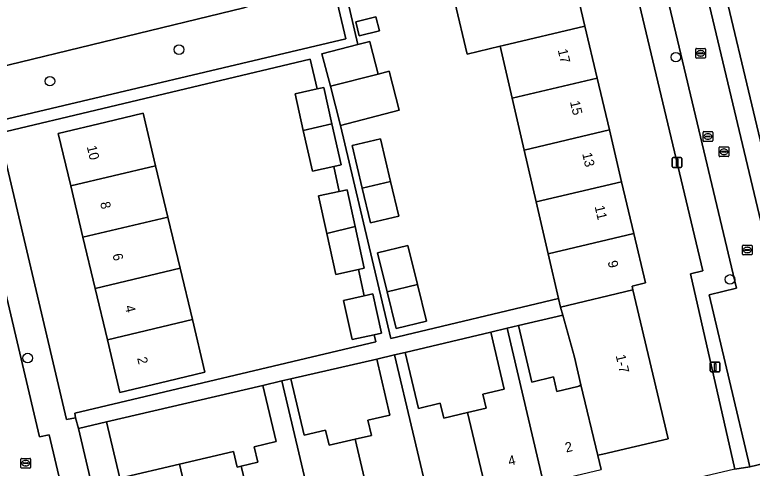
# Model space of a CAD drawing. Extents: x 158472 to 159562, y 388525 to 389606.
# Drawn here: x 159171.7 to 159247.3, y 388576.2 to 388622.7 of the extents above; entities that cross this region are included whole.
import ezdxf

# ---------------------------------------------------------------- set-up
doc = ezdxf.new("R2010")
doc.units = 0
for name, color, linetype in [('IMGEO_Boom', 7, 'Continuous'), ('IMGEO_Erf', 7, 'Continuous'), ('IMGEO_Groenvoorziening', 7, 'Continuous'), ('IMGEO_Kolk', 7, 'Continuous'), ('IMGEO_Lichtmast', 7, 'Continuous'), ('IMGEO_Pand', 7, 'Continuous'), ('IMGEO_Pand_nummerreeks', 7, 'Continuous'), ('IMGEO_Rijbaan_lokaal_open', 7, 'Continuous'), ('IMGEO_Rioolput', 7, 'Continuous'), ('IMGEO_Voetpad_open', 7, 'Continuous')]:
    doc.layers.add(name, color=color, linetype=linetype)

msp = doc.modelspace()

# ---------------------------------------------------------------- linework, layer by layer
at = {"layer": 'IMGEO_Boom'}
for centre in [(159188.531, 388619.113), (159239.452, 388618.341), (159175.308, 388615.879), (159245.003, 388595.558), (159173.023, 388587.499)]:
    msp.add_circle(centre, 0.489, dxfattribs=at)
at = {"layer": 'IMGEO_Erf'}
for points in [[(159296.887, 388671.93), (159244.148, 388659.578), (159237.861, 388658.105), (159242.256, 388639.554), (159241.15, 388639.006), (159241.895, 388635.876), (159249.79, 388602.69), (159251.019, 388602.978), (159251.382, 388603.063), (159252.961, 388596.326), (159253.582, 388593.966)], [(159245.514, 388576.124), (159240.949, 388596.135), (159242.23, 388596.442), (159229.574, 388649.566)], [(159201.454, 388642.922), (159206.868, 388619.642), (159207.813, 388619.885), (159208.079, 388619.953), (159208.123, 388619.781), (159208.936, 388616.616), (159210.069, 388616.907), (159211.098, 388612.898), (159205.074, 388611.351), (159210.232, 388589.51), (159227.434, 388593.617), (159226.379, 388598.185), (159225.149, 388603.504), (159223.918, 388608.825), (159222.688, 388614.145), (159221.459, 388619.464), (159218.069, 388618.665), (159216.817, 388623.98)], [(159228.886, 388626.824), (159230.138, 388621.509), (159231.39, 388616.195), (159232.642, 388610.88), (159233.894, 388605.565), (159235.146, 388600.251), (159236.335, 388595.203), (159234.971, 388594.882), (159235.061, 388594.501), (159238.659, 388579.224), (159231.965, 388577.646), (159231.645, 388577.571), (159231.445, 388577.524), (159231.791, 388576.064)]]:
    msp.add_lwpolyline(points, dxfattribs=at)
for points in [[(159206.652, 388621.955), (159208.709, 388622.473), (159209.071, 388621.035), (159207.014, 388620.518)], [(159203.683, 388600.277), (159202.841, 388604.12), (159204.95, 388604.582), (159204.39, 388607.136), (159202.213, 388606.645), (159201.273, 388610.823), (159200.428, 388614.575), (159202.693, 388615.085), (159201.971, 388618.129), (159170.055, 388610.56), (159177.021, 388581.185), (159177.94, 388581.388), (159177.865, 388581.835), (159208.71, 388589.15), (159208.535, 388589.892), (159206.267, 388589.397), (159205.392, 388593.406), (159207.506, 388593.867), (159206.913, 388596.581), (159204.603, 388596.075)], [(159188.648, 388596.696), (159189.901, 388591.435), (159191.182, 388586.055), (159187.346, 388585.141), (159182.482, 388583.983), (159181.201, 388589.363), (159179.948, 388594.624), (159178.695, 388599.886), (159177.442, 388605.147), (159176.161, 388610.525), (159181.025, 388611.683), (159184.861, 388612.597), (159186.142, 388607.219), (159187.395, 388601.957)], [(159209.176, 388609.966), (159210.207, 388605.595), (159211.047, 388602.037), (159208.145, 388601.352), (159207.306, 388604.912), (159206.275, 388609.281)], [(159212.972, 388595.026), (159213.895, 388591.28), (159210.792, 388590.514), (159209.86, 388594.292), (159208.878, 388598.277), (159211.981, 388599.043)], [(159227.87, 388591.894), (159223.33, 388590.824), (159224.693, 388585.038), (159226.917, 388585.562), (159227.265, 388584.086), (159229.405, 388584.59), (159229.516, 388584.616), (159229.73, 388584.76), (159229.058, 388587.593)], [(159220.494, 388590.156), (159211.727, 388588.073), (159213.077, 388582.342), (159215.311, 388582.869), (159215.674, 388581.328), (159218.116, 388581.903), (159220.023, 388582.352), (159219.68, 388583.807), (159221.869, 388584.323)], [(159208.793, 388587.382), (159199.992, 388585.371), (159201.356, 388579.58), (159203.564, 388580.1), (159203.928, 388578.554), (159206.583, 388579.18), (159208.257, 388579.574), (159207.892, 388581.123), (159210.142, 388581.653)], [(159197.12, 388584.695), (159181.114, 388580.966), (159182.479, 388575.171), (159188.571, 388576.606), (159194.124, 388577.914), (159194.499, 388576.324), (159194.9, 388576.419), (159196.607, 388576.821), (159196.233, 388578.412), (159198.476, 388578.94)]]:
    msp.add_lwpolyline(points, close=True, dxfattribs=at)
at = {"layer": 'IMGEO_Groenvoorziening'}
msp.add_lwpolyline([(159168.435, 388620.55), (159168.696, 388616.985), (159195.192, 388623.391), (159195.688, 388623.56), (159196.139, 388623.829), (159196.524, 388624.186), (159196.826, 388624.615), (159197.032, 388625.097), (159197.134, 388625.611), (159197.042, 388626.545), (159194.87, 388640.508), (159199.815, 388642.509), (159199.819, 388643.8), (159199.82, 388643.968), (159199.978, 388645.419), (159200.286, 388646.845), (159200.742, 388648.231), (159201.34, 388649.562), (159202.074, 388650.824), (159202.936, 388652.001), (159204.476, 388653.608), (159199.027, 388656.284)], dxfattribs=at)
msp.add_lwpolyline([(159169.776, 388611.735), (159205.64, 388620.22), (159200.073, 388643.862), (159199.819, 388643.8), (159199.815, 388642.509), (159194.87, 388640.508), (159197.042, 388626.545), (159197.134, 388625.611), (159197.032, 388625.097), (159196.826, 388624.615), (159196.524, 388624.186), (159196.139, 388623.829), (159195.688, 388623.56), (159195.192, 388623.391), (159168.696, 388616.985)], close=True, dxfattribs=at)
at = {"layer": 'IMGEO_Kolk'}
for p, q in [((159241.488, 388618.31), (159241.488, 388619.162)), ((159241.563, 388619.236), (159242.415, 388619.236)), ((159241.747, 388618.73), (159241.747, 388618.742)), ((159242.185, 388618.693), (159241.787, 388618.693)), ((159241.79, 388618.779), (159242.188, 388618.779)), ((159241.976, 388619.016), (159242.001, 388619.016)), ((159242.231, 388618.742), (159242.231, 388618.73)), ((159242.489, 388619.162), (159242.489, 388618.31)), ((159242.415, 388618.236), (159241.563, 388618.236)), ((159241.999, 388618.456), (159241.974, 388618.456)), ((159243.879, 388608.223), (159243.879, 388609.075)), ((159243.954, 388609.149), (159244.806, 388609.149)), ((159244.367, 388608.929), (159244.392, 388608.929)), ((159244.88, 388609.075), (159244.88, 388608.223)), ((159244.806, 388608.149), (159243.954, 388608.149)), ((159244.138, 388608.643), (159244.138, 388608.655)), ((159244.576, 388608.606), (159244.178, 388608.606)), ((159244.181, 388608.692), (159244.579, 388608.692)), ((159244.39, 388608.369), (159244.365, 388608.369)), ((159244.622, 388608.655), (159244.622, 388608.643)), ((159246.344, 388599.075), (159247.196, 388599.075)), ((159246.269, 388598.149), (159246.269, 388599.001)), ((159246.528, 388598.569), (159246.528, 388598.581)), ((159246.966, 388598.532), (159246.568, 388598.532)), ((159246.571, 388598.618), (159246.969, 388598.618)), ((159246.78, 388598.295), (159246.755, 388598.295)), ((159246.757, 388598.855), (159246.782, 388598.855)), ((159247.012, 388598.581), (159247.012, 388598.569)), ((159247.27, 388599.001), (159247.27, 388598.149)), ((159247.196, 388598.075), (159246.344, 388598.075)), ((159172.321, 388576.292), (159172.321, 388577.144)), ((159172.396, 388577.218), (159173.248, 388577.218)), ((159173.322, 388577.144), (159173.322, 388576.292)), ((159172.58, 388576.712), (159172.58, 388576.724)), ((159173.018, 388576.675), (159172.62, 388576.675)), ((159172.623, 388576.761), (159173.021, 388576.761)), ((159172.832, 388576.438), (159172.807, 388576.438)), ((159172.809, 388576.998), (159172.834, 388576.998)), ((159173.064, 388576.724), (159173.064, 388576.712)), ((159173.248, 388576.218), (159172.396, 388576.218))]:
    msp.add_line(p, q, dxfattribs=at)
for points in [[(159241.488, 388618.31), (159241.488, 388619.162)], [(159241.563, 388619.236), (159242.415, 388619.236)], [(159242.489, 388619.162), (159242.489, 388618.31)], [(159242.415, 388618.236), (159241.563, 388618.236)], [(159243.879, 388608.223), (159243.879, 388609.075)], [(159243.954, 388609.149), (159244.806, 388609.149)], [(159244.88, 388609.075), (159244.88, 388608.223)], [(159244.806, 388608.149), (159243.954, 388608.149)], [(159246.344, 388599.075), (159247.196, 388599.075)], [(159246.269, 388598.149), (159246.269, 388599.001)], [(159247.27, 388599.001), (159247.27, 388598.149)], [(159247.196, 388598.075), (159246.344, 388598.075)], [(159172.321, 388576.292), (159172.321, 388577.144)], [(159172.396, 388577.218), (159173.248, 388577.218)], [(159173.322, 388577.144), (159173.322, 388576.292)], [(159173.248, 388576.218), (159172.396, 388576.218)]]:
    msp.add_lwpolyline(points, dxfattribs=at)
for centre, radius, start, end in [((159241.565, 388619.16), 0.0765, 91.55205, 178.44795), ((159241.565, 388619.16), 0.0765, 91.55205, 178.44795), ((159241.787, 388618.739), 0.0403, 85.87752, 175.75265), ((159241.784, 388618.729), 0.0366, 178.93798, 274.71019), ((159242.188, 388618.736), 0.043, 264.86636, 352.45326), ((159242.192, 388618.741), 0.0386, 1.73085, 96.63898), ((159242.413, 388619.16), 0.0765, 1.55205, 88.44795), ((159242.413, 388619.16), 0.0765, 1.55205, 88.44795), ((159241.565, 388618.312), 0.0765, 181.55205, 268.44795), ((159241.565, 388618.312), 0.0765, 181.55205, 268.44795), ((159242.413, 388618.312), 0.0765, 271.55205, 358.44795), ((159242.413, 388618.312), 0.0765, 271.55205, 358.44795), ((159243.956, 388609.073), 0.0765, 91.55205, 178.44795), ((159243.956, 388609.073), 0.0765, 91.55205, 178.44795), ((159244.804, 388609.073), 0.0765, 1.55205, 88.44795), ((159244.804, 388609.073), 0.0765, 1.55205, 88.44795), ((159243.956, 388608.225), 0.0765, 181.55205, 268.44795), ((159243.956, 388608.225), 0.0765, 181.55205, 268.44795), ((159244.178, 388608.652), 0.0403, 85.87752, 175.75265), ((159244.175, 388608.642), 0.0366, 178.93798, 274.71019), ((159244.579, 388608.649), 0.043, 264.86636, 352.45326), ((159244.583, 388608.654), 0.0386, 1.73085, 96.63898), ((159244.804, 388608.225), 0.0765, 271.55205, 358.44795), ((159244.804, 388608.225), 0.0765, 271.55205, 358.44795), ((159246.346, 388598.999), 0.0765, 91.55205, 178.44795), ((159246.346, 388598.999), 0.0765, 91.55205, 178.44795), ((159247.194, 388598.999), 0.0765, 1.55205, 88.44795), ((159247.194, 388598.999), 0.0765, 1.55205, 88.44795), ((159246.568, 388598.578), 0.0403, 85.87752, 175.75265), ((159246.565, 388598.568), 0.0366, 178.93798, 274.71019), ((159246.969, 388598.575), 0.043, 264.86636, 352.45326), ((159246.973, 388598.58), 0.0386, 1.73085, 96.63898), ((159246.346, 388598.151), 0.0765, 181.55205, 268.44795), ((159246.346, 388598.151), 0.0765, 181.55205, 268.44795), ((159247.194, 388598.151), 0.0765, 271.55205, 358.44795), ((159247.194, 388598.151), 0.0765, 271.55205, 358.44795), ((159172.398, 388577.142), 0.0765, 91.55205, 178.44795), ((159172.398, 388577.142), 0.0765, 91.55205, 178.44795), ((159173.246, 388577.142), 0.0765, 1.55205, 88.44795), ((159173.246, 388577.142), 0.0765, 1.55205, 88.44795), ((159172.62, 388576.721), 0.0403, 85.87752, 175.75265), ((159172.617, 388576.711), 0.0366, 178.93798, 274.71019), ((159173.021, 388576.718), 0.043, 264.86636, 352.45326), ((159173.025, 388576.723), 0.0386, 1.73085, 96.63898), ((159172.398, 388576.294), 0.0765, 181.55205, 268.44795), ((159172.398, 388576.294), 0.0765, 181.55205, 268.44795), ((159173.246, 388576.294), 0.0765, 271.55205, 358.44795), ((159173.246, 388576.294), 0.0765, 271.55205, 358.44795)]:
    msp.add_arc(centre, radius, start, end, dxfattribs=at)
for centre, major_axis, ratio, start_param, end_param in [((159241.975, 388618.736), (-0.387, 0.002), 0.722429, 4.712389, 7.853982), ((159242, 388618.736), (-0.39, 0.002), 0.717154, 1.570796, 4.712389), ((159244.366, 388608.649), (-0.387, 0.002), 0.722429, 4.712389, 7.853982), ((159244.391, 388608.649), (-0.39, 0.002), 0.717154, 1.570796, 4.712389), ((159246.756, 388598.575), (-0.387, 0.002), 0.722429, 4.712389, 7.853982), ((159246.781, 388598.575), (-0.39, 0.002), 0.717154, 1.570796, 4.712389), ((159172.808, 388576.718), (-0.387, 0.002), 0.722429, 4.712389, 7.853982), ((159172.833, 388576.718), (-0.39, 0.002), 0.717154, 1.570796, 4.712389)]:
    msp.add_ellipse(centre, major_axis=major_axis, ratio=ratio, start_param=start_param, end_param=end_param, dxfattribs=at)
at = {"layer": 'IMGEO_Lichtmast'}
for p, q in [((159239.088, 388607.146), (159239.088, 388607.946)), ((159239.088, 388607.946), (159239.088, 388607.146)), ((159239.188, 388608.046), (159239.978, 388608.046)), ((159239.978, 388608.046), (159239.188, 388608.046)), ((159240.078, 388607.946), (159240.078, 388607.146)), ((159240.078, 388607.146), (159240.078, 388607.946)), ((159239.978, 388607.046), (159239.188, 388607.046)), ((159239.188, 388607.046), (159239.978, 388607.046)), ((159242.987, 388586.177), (159242.987, 388586.977)), ((159242.987, 388586.977), (159242.987, 388586.177)), ((159243.087, 388587.077), (159243.877, 388587.077)), ((159243.877, 388587.077), (159243.087, 388587.077)), ((159243.977, 388586.977), (159243.977, 388586.177)), ((159243.977, 388586.177), (159243.977, 388586.977)), ((159243.877, 388586.077), (159243.087, 388586.077)), ((159243.087, 388586.077), (159243.877, 388586.077))]:
    msp.add_line(p, q, dxfattribs=at)
for points in [[(159239.508, 388607.921), (159239.658, 388607.921), (159239.658, 388607.171), (159239.508, 388607.171), (159239.508, 388607.921)], [(159243.407, 388586.952), (159243.557, 388586.952), (159243.557, 388586.202), (159243.407, 388586.202), (159243.407, 388586.952)]]:
    msp.add_lwpolyline(points, dxfattribs=at)
for centre, start, end in [((159239.188, 388607.946), 90, 180), ((159239.188, 388607.946), 90, 180), ((159239.978, 388607.946), 0, 90), ((159239.978, 388607.946), 360, 90), ((159239.188, 388607.146), 180, 270), ((159239.188, 388607.146), 180, 270), ((159239.978, 388607.146), 270, 0), ((159239.978, 388607.146), 270, 0), ((159243.087, 388586.977), 90, 180), ((159243.087, 388586.977), 90, 180), ((159243.877, 388586.977), 0, 90), ((159243.877, 388586.977), 360, 90), ((159243.087, 388586.177), 180, 270), ((159243.087, 388586.177), 180, 270), ((159243.877, 388586.177), 270, 0), ((159243.877, 388586.177), 270, 0)]:
    msp.add_arc(centre, 0.1, start, end, dxfattribs=at)
at = {"layer": 'IMGEO_Pand'}
for points in [[(159228.886, 388626.824), (159220.229, 388624.784), (159216.817, 388623.98), (159218.069, 388618.665), (159221.459, 388619.464), (159221.761, 388619.535), (159230.138, 388621.509)], [(159206.652, 388621.955), (159207.014, 388620.518), (159209.071, 388621.035), (159208.709, 388622.473)], [(159230.138, 388621.509), (159221.761, 388619.535), (159221.459, 388619.464), (159222.688, 388614.145), (159231.39, 388616.195)], [(159208.123, 388619.781), (159208.079, 388619.953), (159207.813, 388619.885), (159206.868, 388619.642), (159203.187, 388618.698), (159204.045, 388615.359), (159208.936, 388616.616)], [(159208.936, 388616.616), (159204.045, 388615.359), (159205.074, 388611.351), (159211.098, 388612.898), (159210.069, 388616.907)], [(159222.688, 388614.145), (159223.918, 388608.825), (159232.642, 388610.88), (159231.39, 388616.195)], [(159203.372, 388615.238), (159202.693, 388615.085), (159200.428, 388614.575), (159201.273, 388610.823), (159204.209, 388611.522)], [(159186.142, 388607.219), (159184.861, 388612.597), (159181.025, 388611.683), (159176.161, 388610.525), (159177.442, 388605.147)], [(159204.209, 388611.522), (159201.273, 388610.823), (159202.213, 388606.645), (159204.39, 388607.136), (159205.158, 388607.309)], [(159225.149, 388603.504), (159233.894, 388605.565), (159232.642, 388610.88), (159223.918, 388608.825)], [(159210.207, 388605.595), (159209.176, 388609.966), (159206.275, 388609.281), (159207.306, 388604.912)], [(159186.142, 388607.219), (159177.442, 388605.147), (159178.695, 388599.886), (159187.395, 388601.957)], [(159210.207, 388605.595), (159207.306, 388604.912), (159208.145, 388601.352), (159211.047, 388602.037)], [(159226.379, 388598.185), (159235.146, 388600.251), (159233.894, 388605.565), (159225.149, 388603.504)], [(159205.753, 388604.758), (159204.95, 388604.582), (159202.841, 388604.12), (159203.683, 388600.277), (159206.583, 388600.968)], [(159188.648, 388596.696), (159187.395, 388601.957), (159178.695, 388599.886), (159179.948, 388594.624)], [(159206.583, 388600.968), (159203.683, 388600.277), (159204.603, 388596.075), (159206.913, 388596.581), (159207.515, 388596.713)], [(159235.146, 388600.251), (159226.379, 388598.185), (159227.434, 388593.617), (159227.639, 388592.731), (159235.061, 388594.501), (159234.971, 388594.882), (159236.335, 388595.203)], [(159209.86, 388594.292), (159212.972, 388595.026), (159211.981, 388599.043), (159208.878, 388598.277)], [(159188.648, 388596.696), (159179.948, 388594.624), (159181.201, 388589.363), (159189.901, 388591.435)], [(159209.86, 388594.292), (159210.792, 388590.514), (159213.895, 388591.28), (159212.972, 388595.026)], [(159235.061, 388594.501), (159227.639, 388592.731), (159227.87, 388591.894), (159229.058, 388587.593), (159229.73, 388584.76), (159231.445, 388577.524), (159231.645, 388577.571), (159231.965, 388577.646), (159238.659, 388579.224)], [(159208.411, 388594.065), (159207.506, 388593.867), (159205.392, 388593.406), (159206.267, 388589.397), (159208.535, 388589.892), (159209.286, 388590.056)], [(159181.201, 388589.363), (159182.482, 388583.983), (159187.346, 388585.141), (159191.182, 388586.055), (159189.901, 388591.435)], [(159229.73, 388584.76), (159229.516, 388584.616), (159229.405, 388584.59), (159227.265, 388584.086), (159226.917, 388585.562), (159224.693, 388585.038), (159223.33, 388590.824), (159222.167, 388590.55), (159225.906, 388574.678), (159231.791, 388576.064), (159231.445, 388577.524)], [(159222.167, 388590.55), (159220.494, 388590.156), (159221.869, 388584.323), (159219.68, 388583.807), (159220.023, 388582.352), (159218.116, 388581.903), (159220.138, 388573.319), (159225.906, 388574.678)], [(159214.371, 388571.961), (159210.636, 388587.816), (159208.793, 388587.382), (159210.142, 388581.653), (159207.892, 388581.123), (159208.257, 388579.574), (159206.583, 388579.18), (159208.604, 388570.602)], [(159214.371, 388571.961), (159220.138, 388573.319), (159218.116, 388581.903), (159215.674, 388581.328), (159215.311, 388582.869), (159213.077, 388582.342), (159211.727, 388588.073), (159210.636, 388587.816)], [(159199.087, 388585.158), (159197.12, 388584.695), (159198.476, 388578.94), (159196.233, 388578.412), (159196.607, 388576.821), (159194.9, 388576.419), (159196.956, 388567.858), (159202.836, 388569.243)], [(159206.583, 388579.18), (159203.928, 388578.554), (159203.564, 388580.1), (159201.356, 388579.58), (159199.992, 388585.371), (159199.087, 388585.158), (159202.836, 388569.243), (159208.604, 388570.602)], [(159190.964, 388566.447), (159188.571, 388576.606), (159182.479, 388575.171), (159181.114, 388580.966), (159178.232, 388580.287), (159181.007, 388568.502), (159183.994, 388569.205), (159184.976, 388565.036), (159188.471, 388565.859)], [(159190.964, 388566.447), (159193.194, 388566.972), (159196.956, 388567.858), (159194.9, 388576.419), (159194.499, 388576.324), (159194.124, 388577.914), (159188.571, 388576.606)]]:
    msp.add_lwpolyline(points, close=True, dxfattribs=at)
at = {"layer": 'IMGEO_Rijbaan_lokaal_open'}
for points in [[(159237.637, 388645.762), (159233.744, 388644.836), (159245.683, 388594.649), (159242.861, 388593.978), (159247.052, 388576.361), (159253.767, 388577.959)], [(159167.373, 388608.491), (159161.72, 388607.241), (159164.57, 388595.141), (159166.293, 388595.522), (159166.762, 388593.532), (159165.038, 388593.151), (159168.127, 388580.036), (159169.851, 388580.417), (159170.357, 388578.269), (159164.637, 388577.004), (159169.077, 388558.152), (159169.142, 388557.878), (159173.898, 388558.93), (159173.799, 388559.349), (159179.702, 388560.654), (159175.232, 388579.635), (159174.222, 388579.412)]]:
    msp.add_lwpolyline(points, close=True, dxfattribs=at)
at = {"layer": 'IMGEO_Rioolput'}
for p, q in [((159242.238, 388609.784), (159242.238, 388610.636)), ((159242.313, 388610.71), (159243.165, 388610.71)), ((159242.726, 388610.49), (159242.751, 388610.49)), ((159243.239, 388610.636), (159243.239, 388609.784)), ((159243.165, 388609.71), (159242.313, 388609.71)), ((159242.497, 388610.204), (159242.497, 388610.216)), ((159242.935, 388610.167), (159242.537, 388610.167)), ((159242.54, 388610.253), (159242.938, 388610.253)), ((159242.749, 388609.93), (159242.724, 388609.93)), ((159242.981, 388610.216), (159242.981, 388610.204))]:
    msp.add_line(p, q, dxfattribs=at)
for points in [[(159242.238, 388609.784), (159242.238, 388610.636)], [(159242.313, 388610.71), (159243.165, 388610.71)], [(159243.239, 388610.636), (159243.239, 388609.784)], [(159243.165, 388609.71), (159242.313, 388609.71)]]:
    msp.add_lwpolyline(points, dxfattribs=at)
for centre, radius, start, end in [((159242.315, 388610.634), 0.0765, 91.55205, 178.44795), ((159242.315, 388610.634), 0.0765, 91.55205, 178.44795), ((159243.163, 388610.634), 0.0765, 1.55205, 88.44795), ((159243.163, 388610.634), 0.0765, 1.55205, 88.44795), ((159242.315, 388609.786), 0.0765, 181.55205, 268.44795), ((159242.315, 388609.786), 0.0765, 181.55205, 268.44795), ((159242.537, 388610.213), 0.0403, 85.87752, 175.75265), ((159242.534, 388610.203), 0.0366, 178.93798, 274.71019), ((159242.938, 388610.21), 0.043, 264.86636, 352.45326), ((159242.942, 388610.215), 0.0386, 1.73085, 96.63898), ((159243.163, 388609.786), 0.0765, 271.55205, 358.44795), ((159243.163, 388609.786), 0.0765, 271.55205, 358.44795)]:
    msp.add_arc(centre, radius, start, end, dxfattribs=at)
for centre, major_axis, ratio, start_param, end_param in [((159242.725, 388610.21), (-0.387, 0.002), 0.722429, 4.712389, 7.853982), ((159242.75, 388610.21), (-0.39, 0.002), 0.717154, 1.570796, 4.712389)]:
    msp.add_ellipse(centre, major_axis=major_axis, ratio=ratio, start_param=start_param, end_param=end_param, dxfattribs=at)
at = {"layer": 'IMGEO_Voetpad_open'}
for points in [[(159242.861, 388593.978), (159245.683, 388594.649), (159233.744, 388644.836), (159237.637, 388645.762), (159239.443, 388646.182), (159236.811, 388657.859), (159237.861, 388658.105), (159244.148, 388659.578), (159242.889, 388664.953), (159232.59, 388662.519), (159232.849, 388661.365), (159233.663, 388657.748), (159233.747, 388657.374)], [(159230.788, 388652.502), (159229.048, 388652.044), (159229.294, 388650.743), (159229.574, 388649.566), (159242.23, 388596.442), (159240.949, 388596.135), (159245.514, 388576.124), (159247.052, 388576.361), (159242.861, 388593.978)], [(159200.073, 388643.862), (159205.64, 388620.22), (159169.776, 388611.735)], [(159170.055, 388610.56), (159201.971, 388618.129), (159202.693, 388615.085), (159203.372, 388615.238), (159204.209, 388611.522), (159205.158, 388607.309), (159204.39, 388607.136), (159204.95, 388604.582), (159205.753, 388604.758), (159206.583, 388600.968), (159207.515, 388596.713), (159206.913, 388596.581), (159207.506, 388593.867), (159208.411, 388594.065), (159209.286, 388590.056), (159208.535, 388589.892), (159208.71, 388589.15), (159177.865, 388581.835), (159177.94, 388581.388), (159178.232, 388580.287), (159181.114, 388580.966), (159197.12, 388584.695), (159199.087, 388585.158), (159199.992, 388585.371), (159208.793, 388587.382), (159210.636, 388587.816), (159211.727, 388588.073), (159220.494, 388590.156), (159222.167, 388590.55), (159223.33, 388590.824), (159227.87, 388591.894), (159227.639, 388592.731), (159227.434, 388593.617), (159210.232, 388589.51), (159205.074, 388611.351), (159204.045, 388615.359), (159203.187, 388618.698), (159206.868, 388619.642), (159201.454, 388642.922)], [(159167.373, 388608.491), (159174.222, 388579.412), (159175.232, 388579.635), (159179.702, 388560.654), (159182.704, 388561.32), (159181.007, 388568.502), (159178.232, 388580.287), (159177.94, 388581.388), (159177.021, 388581.185), (159170.055, 388610.56)], [(159284.448, 388584.604), (159263.015, 388579.505), (159257.184, 388578.118), (159255.718, 388577.769), (159255.567, 388578.404), (159253.767, 388577.959), (159247.052, 388576.361), (159245.514, 388576.124), (159182.704, 388561.32), (159179.702, 388560.654), (159173.799, 388559.349), (159173.898, 388558.93), (159169.142, 388557.878), (159169.077, 388558.152), (159168.333, 388557.977), (159149.026, 388553.544)]]:
    msp.add_lwpolyline(points, dxfattribs=at)
msp.add_lwpolyline([(159241.895, 388635.876), (159241.15, 388639.006), (159239.443, 388646.182), (159237.637, 388645.762), (159253.767, 388577.959), (159255.567, 388578.404), (159251.402, 388595.915), (159249.79, 388602.69)], close=True, dxfattribs=at)

# ---------------------------------------------------------------- texts
at = {"layer": 'IMGEO_Pand_nummerreeks'}
for s, rotation, p in [('17', 283.25803, (159227.342, 388619.071)), ('15', 283.25517, (159228.594, 388613.76)), ('10', 283.39551, (159179.075, 388609.167)), ('13', 283.25517, (159229.846, 388608.448)), ('8', 283.39551, (159180.445, 388603.41)), ('11', 283.25517, (159231.123, 388603.024)), ('6', 283.39551, (159181.709, 388598.106)), ('9', 283.25803, (159232.454, 388597.375)), ('4', 283.39551, (159182.973, 388592.797)), ('1-7', 283.2523, (159233.282, 388587.743)), ('2', 283.39551, (159184.237, 388587.491)), ('2', 13.25824, (159228.222, 388577.813)), ('4', 13.25593, (159222.385, 388576.437))]:
    msp.add_text(s, height=1, rotation=rotation, dxfattribs=at).set_placement(p)

doc.saveas('drawing.dxf')
